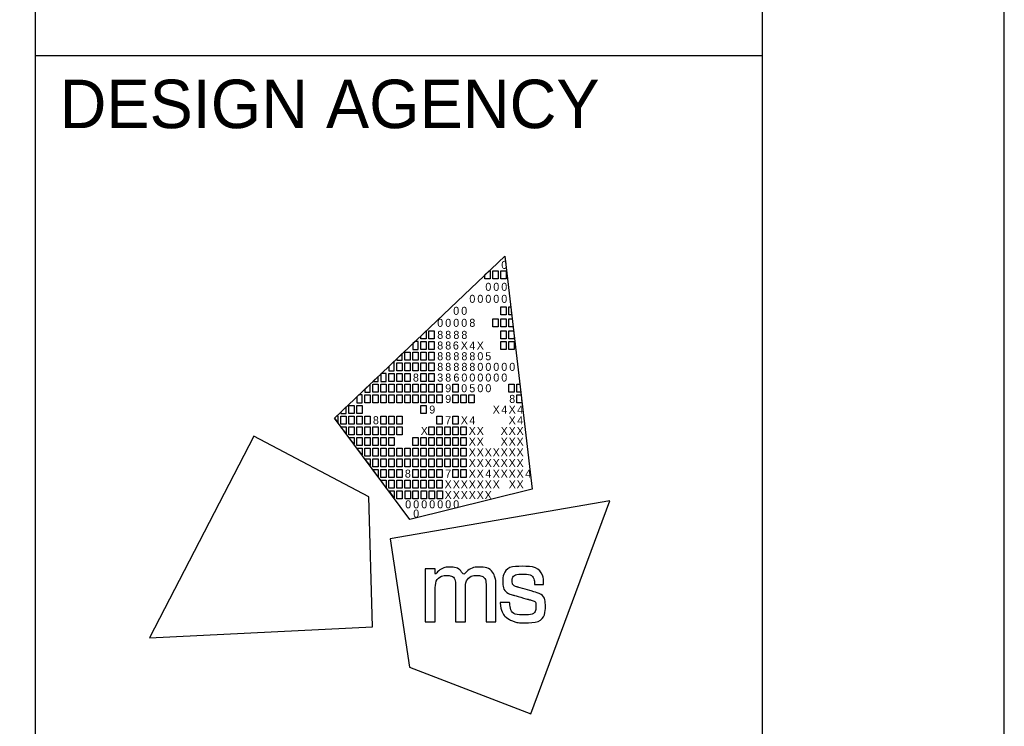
# Model space of a CAD drawing. Extents: x 0 to 34, y 0 to 22.
# Drawn here: x 31.968 to 34, y 3.616 to 5.074 of the extents above; entities that cross this region are included whole.
import ezdxf

# ---------------------------------------------------------------- set-up
doc = ezdxf.new("R2010")
doc.units = 0
for name, color, linetype in [('SH_Border', 7, 'Continuous'), ('SH_Cut_Line', 7, 'Continuous'), ('SH_Data', 7, 'Continuous')]:
    doc.layers.add(name, color=color, linetype=linetype)

msp = doc.modelspace()

# ---------------------------------------------------------------- linework, layer by layer
at = {"layer": 'SH_Border'}
for p, q in [((32, 0.5), (32, 21.5)), ((32, 5), (33.5, 5)), ((32.6175, 4.2519), (32.9688, 4.5861)), ((32.9688, 4.5861), (32.9688, 4.5861)), ((32.9688, 4.5861), (33.0253, 4.1052)), ((32.773, 4.043), (32.6175, 4.2519)), ((33.0253, 4.1052), (32.773, 4.043))]:
    msp.add_line(p, q, dxfattribs=at)
for points in [[(1.5, 21.5), (33.5, 21.5), (33.5, 0.5), (1.5, 0.5)], [(32.9279, 4.5472), (32.9369, 4.5558), (32.9389, 4.5558), (32.9389, 4.5393), (32.9279, 4.5393)], [(32.9444, 4.5558), (32.9554, 4.5558), (32.9554, 4.5393), (32.9444, 4.5393)], [(32.9609, 4.5558), (32.9719, 4.5558), (32.9719, 4.5393), (32.9609, 4.5393)], [(32.9606, 4.4815), (32.9716, 4.4815), (32.9716, 4.465), (32.9606, 4.465)], [(32.9771, 4.4815), (32.9811, 4.4815), (32.983, 4.465), (32.9771, 4.465)], [(32.9441, 4.4567), (32.9551, 4.4567), (32.9551, 4.4402), (32.9441, 4.4402)], [(32.9606, 4.4567), (32.9716, 4.4567), (32.9716, 4.4402), (32.9606, 4.4402)], [(32.9771, 4.4567), (32.984, 4.4567), (32.9859, 4.4402), (32.9771, 4.4402)], [(32.7953, 4.4211), (32.8064, 4.4316), (32.8064, 4.4154), (32.7953, 4.4154)], [(32.8123, 4.4319), (32.8233, 4.4319), (32.8233, 4.4154), (32.8123, 4.4154)], [(32.9606, 4.4319), (32.9716, 4.4319), (32.9716, 4.4154), (32.9606, 4.4154)], [(32.9771, 4.4319), (32.9869, 4.4319), (32.9881, 4.4218), (32.9881, 4.4154), (32.9771, 4.4154)], [(32.7958, 4.4099), (32.8068, 4.4099), (32.8068, 4.3934), (32.7958, 4.3934)], [(32.8123, 4.4099), (32.8233, 4.4099), (32.8233, 4.3934), (32.8123, 4.3934)], [(32.9606, 4.4099), (32.9716, 4.4099), (32.9716, 4.3934), (32.9606, 4.3934)], [(32.9771, 4.4099), (32.9881, 4.4099), (32.9881, 4.3934), (32.9771, 4.3934)], [(32.7627, 4.3879), (32.7737, 4.3879), (32.7737, 4.3714), (32.7627, 4.3714)], [(32.7793, 4.3879), (32.7903, 4.3879), (32.7903, 4.3714), (32.7793, 4.3714)], [(32.7958, 4.3879), (32.8068, 4.3879), (32.8068, 4.3714), (32.7958, 4.3714)], [(32.8123, 4.3879), (32.8233, 4.3879), (32.8233, 4.3714), (32.8123, 4.3714)], [(32.7462, 4.3659), (32.7572, 4.3659), (32.7572, 4.3494), (32.7462, 4.3494)], [(32.7627, 4.3659), (32.7737, 4.3659), (32.7737, 4.3494), (32.7627, 4.3494)], [(32.7793, 4.3659), (32.7903, 4.3659), (32.7903, 4.3494), (32.7793, 4.3494)], [(32.7958, 4.3659), (32.8068, 4.3659), (32.8068, 4.3494), (32.7958, 4.3494)], [(32.8123, 4.3659), (32.8233, 4.3659), (32.8233, 4.3494), (32.8123, 4.3494)], [(32.7297, 4.3439), (32.7407, 4.3439), (32.7407, 4.3273), (32.7297, 4.3273)], [(32.7462, 4.3439), (32.7572, 4.3439), (32.7572, 4.3273), (32.7462, 4.3273)], [(32.7627, 4.3439), (32.7737, 4.3439), (32.7737, 4.3273), (32.7627, 4.3273)], [(32.7958, 4.3439), (32.8068, 4.3439), (32.8068, 4.3273), (32.7958, 4.3273)], [(32.8123, 4.3439), (32.8233, 4.3439), (32.8233, 4.3273), (32.8123, 4.3273)], [(32.6967, 4.3218), (32.7077, 4.3218), (32.7077, 4.3053), (32.6967, 4.3053)], [(32.7132, 4.3218), (32.7242, 4.3218), (32.7242, 4.3053), (32.7132, 4.3053)], [(32.7297, 4.3218), (32.7407, 4.3218), (32.7407, 4.3053), (32.7297, 4.3053)], [(32.7462, 4.3218), (32.7572, 4.3218), (32.7572, 4.3053), (32.7462, 4.3053)], [(32.7627, 4.3218), (32.7737, 4.3218), (32.7737, 4.3053), (32.7627, 4.3053)], [(32.7793, 4.3218), (32.7903, 4.3218), (32.7903, 4.3053), (32.7793, 4.3053)], [(32.7958, 4.3218), (32.8068, 4.3218), (32.8068, 4.3053), (32.7958, 4.3053)], [(32.8123, 4.3218), (32.8233, 4.3218), (32.8233, 4.3053), (32.8123, 4.3053)], [(32.8288, 4.3218), (32.8398, 4.3218), (32.8398, 4.3053), (32.8288, 4.3053)], [(32.8618, 4.3218), (32.8728, 4.3218), (32.8728, 4.3053), (32.8618, 4.3053)], [(32.9771, 4.3218), (32.9881, 4.3218), (32.9881, 4.3053), (32.9771, 4.3053)], [(32.9935, 4.3218), (32.9998, 4.3218), (33.0018, 4.3053), (32.9935, 4.3053)], [(32.6802, 4.2998), (32.6912, 4.2998), (32.6912, 4.2833), (32.6802, 4.2833)], [(32.6967, 4.2998), (32.7077, 4.2998), (32.7077, 4.2833), (32.6967, 4.2833)], [(32.7132, 4.2998), (32.7242, 4.2998), (32.7242, 4.2833), (32.7132, 4.2833)], [(32.7297, 4.2998), (32.7407, 4.2998), (32.7407, 4.2833), (32.7297, 4.2833)], [(32.7462, 4.2998), (32.7572, 4.2998), (32.7572, 4.2833), (32.7462, 4.2833)], [(32.7627, 4.2998), (32.7737, 4.2998), (32.7737, 4.2833), (32.7627, 4.2833)], [(32.7793, 4.2998), (32.7903, 4.2998), (32.7903, 4.2833), (32.7793, 4.2833)], [(32.7958, 4.2998), (32.8068, 4.2998), (32.8068, 4.2833), (32.7958, 4.2833)], [(32.8123, 4.2998), (32.8233, 4.2998), (32.8233, 4.2833), (32.8123, 4.2833)], [(32.8288, 4.2998), (32.8398, 4.2998), (32.8398, 4.2833), (32.8288, 4.2833)], [(32.8618, 4.2998), (32.8728, 4.2998), (32.8728, 4.2833), (32.8618, 4.2833)], [(32.8783, 4.2998), (32.8893, 4.2998), (32.8893, 4.2833), (32.8783, 4.2833)], [(32.8947, 4.2998), (32.9057, 4.2998), (32.9057, 4.2833), (32.8947, 4.2833)], [(32.9935, 4.2998), (33.0024, 4.2998), (33.0044, 4.2833), (32.9935, 4.2833)], [(32.6471, 4.2778), (32.6581, 4.2778), (32.6581, 4.2613), (32.6471, 4.2613)], [(32.6637, 4.2778), (32.6747, 4.2778), (32.6747, 4.2613), (32.6637, 4.2613)], [(32.7958, 4.2778), (32.8068, 4.2778), (32.8068, 4.2613), (32.7958, 4.2613)], [(32.6306, 4.2558), (32.6416, 4.2558), (32.6416, 4.2393), (32.6306, 4.2393)], [(32.6471, 4.2558), (32.6581, 4.2558), (32.6581, 4.2393), (32.6471, 4.2393)], [(32.6637, 4.2558), (32.6747, 4.2558), (32.6747, 4.2393), (32.6637, 4.2393)], [(32.6802, 4.2558), (32.6912, 4.2558), (32.6912, 4.2393), (32.6802, 4.2393)], [(32.7132, 4.2558), (32.7242, 4.2558), (32.7242, 4.2393), (32.7132, 4.2393)], [(32.7297, 4.2558), (32.7407, 4.2558), (32.7407, 4.2393), (32.7297, 4.2393)], [(32.7462, 4.2558), (32.7572, 4.2558), (32.7572, 4.2393), (32.7462, 4.2393)], [(32.8288, 4.2558), (32.8398, 4.2558), (32.8398, 4.2393), (32.8288, 4.2393)], [(32.8618, 4.2558), (32.8728, 4.2558), (32.8728, 4.2393), (32.8618, 4.2393)], [(32.6306, 4.2338), (32.6416, 4.2338), (32.6416, 4.22)], [(32.6471, 4.2338), (32.6581, 4.2338), (32.6581, 4.2173), (32.6471, 4.2173)], [(32.6637, 4.2338), (32.6747, 4.2338), (32.6747, 4.2173), (32.6637, 4.2173)], [(32.6802, 4.2338), (32.6912, 4.2338), (32.6912, 4.2173), (32.6802, 4.2173)], [(32.6967, 4.2338), (32.7077, 4.2338), (32.7077, 4.2173), (32.6967, 4.2173)], [(32.7132, 4.2338), (32.7242, 4.2338), (32.7242, 4.2173), (32.7132, 4.2173)], [(32.7297, 4.2338), (32.7407, 4.2338), (32.7407, 4.2173), (32.7297, 4.2173)], [(32.7462, 4.2338), (32.7572, 4.2338), (32.7572, 4.2173), (32.7462, 4.2173)], [(32.8123, 4.2338), (32.8233, 4.2338), (32.8233, 4.2173), (32.8123, 4.2173)], [(32.8288, 4.2338), (32.8398, 4.2338), (32.8398, 4.2173), (32.8288, 4.2173)], [(32.8453, 4.2338), (32.8563, 4.2338), (32.8563, 4.2173), (32.8453, 4.2173)], [(32.8618, 4.2338), (32.8728, 4.2338), (32.8728, 4.2173), (32.8618, 4.2173)], [(32.8783, 4.2338), (32.8893, 4.2338), (32.8893, 4.2173), (32.8783, 4.2173)], [(32.6471, 4.2117), (32.6581, 4.2117), (32.6581, 4.198)], [(32.6637, 4.2117), (32.6747, 4.2117), (32.6747, 4.1952), (32.6637, 4.1952)], [(32.6802, 4.2117), (32.6912, 4.2117), (32.6912, 4.1952), (32.6802, 4.1952)], [(32.6967, 4.2117), (32.7077, 4.2117), (32.7077, 4.1952), (32.6967, 4.1952)], [(32.7132, 4.2117), (32.7242, 4.2117), (32.7242, 4.1952), (32.7132, 4.1952)], [(32.7297, 4.2117), (32.7407, 4.2117), (32.7407, 4.1952), (32.7297, 4.1952)], [(32.7793, 4.2117), (32.7903, 4.2117), (32.7903, 4.1952), (32.7793, 4.1952)], [(32.7958, 4.2117), (32.8068, 4.2117), (32.8068, 4.1952), (32.7958, 4.1952)], [(32.8123, 4.2117), (32.8233, 4.2117), (32.8233, 4.1952), (32.8123, 4.1952)], [(32.8288, 4.2117), (32.8398, 4.2117), (32.8398, 4.1952), (32.8288, 4.1952)], [(32.8453, 4.2117), (32.8563, 4.2117), (32.8563, 4.1952), (32.8453, 4.1952)], [(32.8618, 4.2117), (32.8728, 4.2117), (32.8728, 4.1952), (32.8618, 4.1952)], [(32.8783, 4.2117), (32.8893, 4.2117), (32.8893, 4.1952), (32.8783, 4.1952)], [(32.6637, 4.1897), (32.6747, 4.1897), (32.6747, 4.176)], [(32.6747, 4.1897), (32.6747, 4.1897), (32.6747, 4.1897)], [(32.6802, 4.1897), (32.6912, 4.1897), (32.6912, 4.1732), (32.6802, 4.1732)], [(32.6967, 4.1897), (32.7077, 4.1897), (32.7077, 4.1732), (32.6967, 4.1732)], [(32.7132, 4.1897), (32.7242, 4.1897), (32.7242, 4.1732), (32.7132, 4.1732)], [(32.7297, 4.1897), (32.7407, 4.1897), (32.7407, 4.1732), (32.7297, 4.1732)], [(32.7462, 4.1897), (32.7572, 4.1897), (32.7572, 4.1732), (32.7462, 4.1732)], [(32.7627, 4.1897), (32.7737, 4.1897), (32.7737, 4.1732), (32.7627, 4.1732)], [(32.7793, 4.1897), (32.7903, 4.1897), (32.7903, 4.1732), (32.7793, 4.1732)], [(32.7958, 4.1897), (32.8068, 4.1897), (32.8068, 4.1732), (32.7958, 4.1732)], [(32.8123, 4.1897), (32.8233, 4.1897), (32.8233, 4.1732), (32.8123, 4.1732)], [(32.8288, 4.1897), (32.8398, 4.1897), (32.8398, 4.1732), (32.8288, 4.1732)], [(32.8453, 4.1897), (32.8563, 4.1897), (32.8563, 4.1732), (32.8453, 4.1732)], [(32.8618, 4.1897), (32.8728, 4.1897), (32.8728, 4.1732), (32.8618, 4.1732)], [(32.8783, 4.1897), (32.8893, 4.1897), (32.8893, 4.1732), (32.8783, 4.1732)], [(32.6802, 4.1677), (32.6912, 4.1677), (32.6912, 4.154)], [(32.6967, 4.1677), (32.7077, 4.1677), (32.7077, 4.1512), (32.6967, 4.1512)], [(32.7132, 4.1677), (32.7242, 4.1677), (32.7242, 4.1512), (32.7132, 4.1512)], [(32.7297, 4.1677), (32.7407, 4.1677), (32.7407, 4.1512), (32.7297, 4.1512)], [(32.7462, 4.1677), (32.7572, 4.1677), (32.7572, 4.1512), (32.7462, 4.1512)], [(32.7627, 4.1677), (32.7737, 4.1677), (32.7737, 4.1512), (32.7627, 4.1512)], [(32.7793, 4.1677), (32.7903, 4.1677), (32.7903, 4.1512), (32.7793, 4.1512)], [(32.7958, 4.1677), (32.8068, 4.1677), (32.8068, 4.1512), (32.7958, 4.1512)], [(32.8123, 4.1677), (32.8233, 4.1677), (32.8233, 4.1512), (32.8123, 4.1512)], [(32.8288, 4.1677), (32.8398, 4.1677), (32.8398, 4.1512), (32.8288, 4.1512)], [(32.8453, 4.1677), (32.8563, 4.1677), (32.8563, 4.1512), (32.8453, 4.1512)], [(32.8618, 4.1677), (32.8728, 4.1677), (32.8728, 4.1512), (32.8618, 4.1512)], [(32.8783, 4.1677), (32.8893, 4.1677), (32.8893, 4.1512), (32.8783, 4.1512)], [(32.7077, 4.1305), (32.6965, 4.1457), (32.7077, 4.1457)], [(32.7132, 4.1457), (32.7242, 4.1457), (32.7242, 4.1292), (32.7132, 4.1292)], [(32.7297, 4.1457), (32.7407, 4.1457), (32.7407, 4.1292), (32.7297, 4.1292)], [(32.7462, 4.1457), (32.7572, 4.1457), (32.7572, 4.1292), (32.7462, 4.1292)], [(32.7793, 4.1457), (32.7903, 4.1457), (32.7903, 4.1292), (32.7793, 4.1292)], [(32.7958, 4.1457), (32.8068, 4.1457), (32.8068, 4.1292), (32.7958, 4.1292)], [(32.8123, 4.1457), (32.8233, 4.1457), (32.8233, 4.1292), (32.8123, 4.1292)], [(32.8288, 4.1457), (32.8398, 4.1457), (32.8398, 4.1292), (32.8288, 4.1292)], [(32.8618, 4.1457), (32.8728, 4.1457), (32.8728, 4.1292), (32.8618, 4.1292)], [(32.8783, 4.1457), (32.8893, 4.1457), (32.8893, 4.1292), (32.8783, 4.1292)], [(32.724, 4.1082), (32.7132, 4.1237), (32.7242, 4.1237)], [(32.7297, 4.1237), (32.7407, 4.1237), (32.7407, 4.1072), (32.7297, 4.1072)], [(32.7462, 4.1237), (32.7572, 4.1237), (32.7572, 4.1072), (32.7462, 4.1072)], [(32.7627, 4.1237), (32.7737, 4.1237), (32.7737, 4.1072), (32.7627, 4.1072)], [(32.7793, 4.1237), (32.7903, 4.1237), (32.7903, 4.1072), (32.7793, 4.1072)], [(32.7958, 4.1237), (32.8068, 4.1237), (32.8068, 4.1072), (32.7958, 4.1072)], [(32.8123, 4.1237), (32.8233, 4.1237), (32.8233, 4.1072), (32.8123, 4.1072)], [(32.8288, 4.1237), (32.8398, 4.1237), (32.8398, 4.1072), (32.8288, 4.1072)], [(32.7302, 4.1017), (32.7407, 4.1017), (32.7408, 4.0875)], [(32.7463, 4.1017), (32.7573, 4.1017), (32.7573, 4.0852), (32.7463, 4.0852)], [(32.763, 4.1017), (32.774, 4.1017), (32.774, 4.0852), (32.763, 4.0852)], [(32.7794, 4.1017), (32.7904, 4.1017), (32.7904, 4.0852), (32.7794, 4.0852)], [(32.796, 4.1017), (32.807, 4.1017), (32.807, 4.0852), (32.796, 4.0852)], [(32.8129, 4.1017), (32.8239, 4.1017), (32.8239, 4.0851), (32.8129, 4.0851)], [(32.8296, 4.1017), (32.8406, 4.1017), (32.8406, 4.0851), (32.8296, 4.0851)]]:
    msp.add_lwpolyline(points, close=True, dxfattribs=at)
for points in [[(32.7903, 4.4099), (32.7836, 4.4099), (32.7793, 4.4058), (32.7793, 4.3934), (32.7903, 4.3934), (32.7903, 4.4099)], [(32.7572, 4.3849), (32.7462, 4.3744), (32.7462, 4.3714), (32.7572, 4.3714), (32.7572, 4.3849)], [(32.7407, 4.3691), (32.7297, 4.3587), (32.7297, 4.3494), (32.7407, 4.3494), (32.7407, 4.3691)], [(32.7077, 4.3377), (32.6968, 4.3273), (32.7077, 4.3273), (32.7077, 4.3377)], [(32.7242, 4.3439), (32.7141, 4.3439), (32.7132, 4.343), (32.7132, 4.3273), (32.7242, 4.3273), (32.7242, 4.3439)], [(32.6912, 4.322), (32.6802, 4.3115), (32.6802, 4.3053), (32.6912, 4.3053), (32.6912, 4.322)], [(32.6747, 4.2998), (32.6679, 4.2998), (32.6637, 4.2958), (32.6637, 4.2833), (32.6747, 4.2833), (32.6747, 4.2998)], [(32.6416, 4.2749), (32.6306, 4.2644), (32.6306, 4.2613), (32.6416, 4.2613), (32.6416, 4.2749)], [(32.6251, 4.2558), (32.6216, 4.2558), (32.6175, 4.2519), (32.6251, 4.2417), (32.6251, 4.2558)], [(32.4512, 4.2149), (32.2359, 3.7988), (32.6956, 3.8215), (32.6884, 4.0892), (32.4512, 4.2149)], [(33.0229, 3.6422), (33.1859, 4.0814), (32.7324, 4.0029), (32.7722, 3.7381), (33.0229, 3.6422)]]:
    msp.add_lwpolyline(points, dxfattribs=at)
for points in [[(32.8048, 3.8315), (32.8048, 3.8315), (32.8048, 3.9409), (32.8048, 3.9409), (32.8048, 3.9409), (32.8255, 3.9409), (32.8255, 3.9409), (32.8255, 3.9409), (32.8255, 3.9297), (32.8255, 3.9297), (32.8346, 3.9399), (32.8457, 3.9445), (32.8555, 3.9445), (32.8688, 3.9445), (32.8791, 3.9372), (32.8837, 3.9266), (32.8915, 3.9381), (32.905, 3.9446), (32.9166, 3.9446), (32.9325, 3.9446), (32.9451, 3.935), (32.9494, 3.9213), (32.9494, 3.9212), (32.9494, 3.9212), (32.9494, 3.9212), (32.9501, 3.919), (32.9506, 3.9172), (32.9506, 3.9071), (32.9506, 3.9071), (32.9506, 3.8314), (32.9506, 3.8314), (32.9506, 3.8314), (32.9303, 3.8314), (32.9303, 3.8314), (32.9303, 3.8314), (32.9303, 3.9048), (32.9303, 3.9048), (32.9303, 3.9201), (32.9219, 3.9274), (32.911, 3.9274), (32.8995, 3.9274), (32.8879, 3.9171), (32.8879, 3.9001), (32.8879, 3.9001), (32.8879, 3.8315), (32.8879, 3.8315), (32.8879, 3.8315), (32.8674, 3.8315), (32.8674, 3.8315), (32.8674, 3.8315), (32.8674, 3.9059), (32.8674, 3.9059), (32.8674, 3.9203), (32.8588, 3.9274), (32.8496, 3.9274), (32.8384, 3.9274), (32.8254, 3.917), (32.8254, 3.8962), (32.8254, 3.8962), (32.8254, 3.8315), (32.8254, 3.8315), (32.8254, 3.8315), (32.8048, 3.8315), (32.8048, 3.8315)], [(32.9595, 3.8709), (32.9595, 3.8709), (32.9595, 3.8717), (32.9595, 3.8717), (32.9595, 3.8717), (32.9603, 3.8717), (32.9603, 3.8717), (32.9603, 3.8717), (32.9783, 3.8717), (32.9783, 3.8717), (32.9783, 3.8717), (32.9789, 3.8717), (32.9789, 3.8717), (32.9789, 3.8717), (32.979, 3.871), (32.979, 3.871), (32.9803, 3.8554), (32.9887, 3.846), (33.009, 3.846), (33.0273, 3.846), (33.0333, 3.8554), (33.0333, 3.8631), (33.0333, 3.8732), (33.0256, 3.8758), (33.0175, 3.878), (33.0175, 3.878), (32.987, 3.8867), (32.987, 3.8867), (32.972, 3.8909), (32.9648, 3.9019), (32.9648, 3.9142), (32.9648, 3.9303), (32.9768, 3.9462), (33.0052, 3.9462), (33.0348, 3.9462), (33.0489, 3.9285), (33.0489, 3.9095), (33.0489, 3.9095), (33.0489, 3.9087), (33.0489, 3.9087), (33.0489, 3.9087), (33.0482, 3.9087), (33.0482, 3.9087), (33.0482, 3.9087), (33.0312, 3.9087), (33.0312, 3.9087), (33.0312, 3.9087), (33.0305, 3.9087), (33.0305, 3.9087), (33.0305, 3.9087), (33.0305, 3.9094), (33.0305, 3.9094), (33.0301, 3.9208), (33.0226, 3.93), (33.0056, 3.93), (32.9891, 3.93), (32.9843, 3.9218), (32.9843, 3.9157), (32.9843, 3.9108), (32.9869, 3.9059), (32.9959, 3.9033), (32.9959, 3.9033), (33.0255, 3.8948), (33.0255, 3.8948), (33.0462, 3.8889), (33.0527, 3.8777), (33.0527, 3.8639), (33.0527, 3.8462), (33.041, 3.8298), (33.0087, 3.8298), (32.9952, 3.8298), (32.9877, 3.8321), (32.9823, 3.8348), (32.969, 3.8414), (32.9609, 3.8536), (32.9595, 3.8709)]]:
    msp.add_open_spline(points, degree=3, dxfattribs=at)
at = {"layer": 'SH_Cut_Line'}
msp.add_lwpolyline([(0, 0), (34, 0), (34, 22), (0, 22)], close=True, dxfattribs=at)
at = {"layer": 'SH_Data'}
msp.add_line((32.75, 4), (32.75, 4), dxfattribs=at)

# ---------------------------------------------------------------- texts
at = {"layer": 'SH_Border'}
for s, p in [('0', (32.9617, 4.5597)), ('0', (32.9288, 4.5145)), ('0', (32.9452, 4.5145)), ('0', (32.9617, 4.5145)), ('0', (32.8958, 4.4897)), ('0', (32.9123, 4.4897)), ('0', (32.9288, 4.4897)), ('0', (32.9452, 4.4897)), ('0', (32.9617, 4.4897)), ('0', (32.8625, 4.465)), ('0', (32.879, 4.465)), ('0', (32.8295, 4.4402)), ('0', (32.846, 4.4402)), ('0', (32.8625, 4.4402)), ('0', (32.879, 4.4402)), ('8', (32.8958, 4.4402)), ('8', (32.8295, 4.4154)), ('8', (32.846, 4.4154)), ('8', (32.8628, 4.4154)), ('8', (32.8793, 4.4154)), ('8', (32.8295, 4.3934)), ('8', (32.846, 4.3934)), ('6', (32.8618, 4.3934)), ('X', (32.8781, 4.3934)), ('4', (32.8958, 4.3934)), ('X', (32.911, 4.3934)), ('8', (32.8295, 4.3713)), ('8', (32.846, 4.3713)), ('8', (32.8628, 4.3713)), ('8', (32.8794, 4.3713)), ('8', (32.8958, 4.3713)), ('0', (32.9123, 4.3713)), ('5', (32.9287, 4.3713)), ('8', (32.8295, 4.3494)), ('8', (32.846, 4.3494)), ('8', (32.8628, 4.3494)), ('8', (32.8794, 4.3494)), ('8', (32.8958, 4.3494)), ('0', (32.9123, 4.3494)), ('0', (32.9288, 4.3494)), ('0', (32.9452, 4.3494)), ('0', (32.9617, 4.3494)), ('0', (32.9782, 4.3494)), ('8', (32.7793, 4.3273)), ('3', (32.8295, 4.3273)), ('8', (32.846, 4.3273)), ('6', (32.8629, 4.3273)), ('0', (32.8793, 4.3273)), ('0', (32.8958, 4.3273)), ('0', (32.9123, 4.3273)), ('0', (32.9288, 4.3273)), ('0', (32.9452, 4.3273)), ('0', (32.9617, 4.3273)), ('9', (32.846, 4.3053)), ('0', (32.879, 4.3053)), ('5', (32.8957, 4.3053)), ('0', (32.9123, 4.3053)), ('0', (32.9288, 4.3053)), ('9', (32.846, 4.2833)), ('8', (32.9781, 4.2833)), ('9', (32.813, 4.2613)), ('X', (32.9439, 4.2613)), ('4', (32.9617, 4.2613)), ('X', (32.9769, 4.2613)), ('4', (32.9946, 4.2613)), ('8', (32.6967, 4.2393)), ('7', (32.846, 4.2393)), ('X', (32.8781, 4.2393)), ('4', (32.8958, 4.2393)), ('X', (32.9769, 4.2393)), ('4', (32.9946, 4.2393)), ('X', (32.7955, 4.2173)), ('X', (32.8945, 4.2173)), ('X', (32.911, 4.2173)), ('X', (32.9604, 4.2173)), ('X', (32.9769, 4.2173)), ('X', (32.9933, 4.2173)), ('X', (32.8945, 4.1952)), ('X', (32.911, 4.1952)), ('X', (32.9604, 4.1952)), ('X', (32.9769, 4.1952)), ('X', (32.9933, 4.1952)), ('X', (32.8945, 4.1732)), ('X', (32.911, 4.1732)), ('X', (32.9274, 4.1732)), ('X', (32.9439, 4.1732)), ('X', (32.9604, 4.1732)), ('X', (32.9769, 4.1732)), ('X', (32.9933, 4.1732)), ('X', (32.8945, 4.1512)), ('X', (32.911, 4.1512)), ('X', (32.9274, 4.1512)), ('X', (32.9439, 4.1512)), ('X', (32.9604, 4.1512)), ('X', (32.9769, 4.1512)), ('X', (32.9933, 4.1512)), ('8', (32.7627, 4.1292)), ('7', (32.846, 4.1292)), ('X', (32.8945, 4.1292)), ('X', (32.911, 4.1292)), ('4', (32.9288, 4.1292)), ('X', (32.9439, 4.1292)), ('X', (32.9604, 4.1292)), ('X', (32.9769, 4.1292)), ('X', (32.9933, 4.1292)), ('4', (33.0111, 4.1292)), ('X', (32.8447, 4.1072)), ('X', (32.8616, 4.1072)), ('X', (32.878, 4.1072)), ('X', (32.8945, 4.1072)), ('X', (32.911, 4.1072)), ('X', (32.9274, 4.1072)), ('X', (32.9439, 4.1072)), ('X', (32.9771, 4.1072)), ('X', (32.9933, 4.1072)), ('X', (32.8447, 4.0851)), ('X', (32.8616, 4.0851)), ('X', (32.878, 4.0851)), ('X', (32.8945, 4.0851)), ('X', (32.911, 4.0851)), ('X', (32.9274, 4.0851)), ('0', (32.7634, 4.0659)), ('0', (32.7799, 4.0659)), ('0', (32.7965, 4.0659)), ('0', (32.813, 4.0659)), ('0', (32.8295, 4.0659)), ('0', (32.846, 4.0659)), ('0', (32.8625, 4.0659)), ('0', (32.7799, 4.0467))]:
    msp.add_text(s, height=0.0165, rotation=360, dxfattribs=at).set_placement(p)
at = {"layer": 'SH_Data'}
msp.add_text('DESIGN AGENCY', height=0.1, dxfattribs=at).set_placement((32.05, 4.85))

doc.saveas('drawing.dxf')
